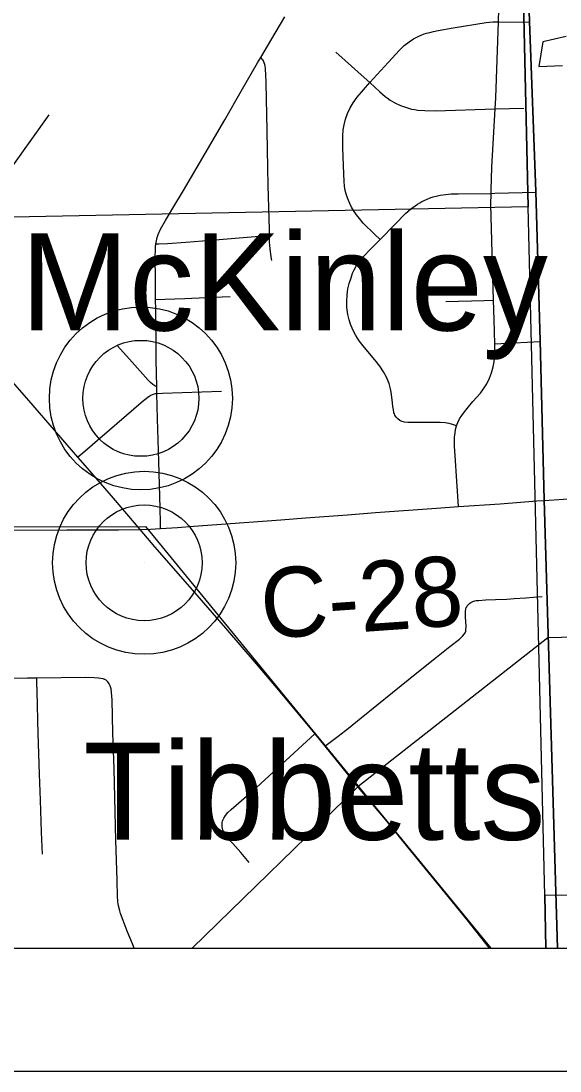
# Model space of a CAD drawing. Extents: x -6.4 to 34, y -4.2 to 22.
# Drawn here: x 6.676 to 7.115, y 14 to 14.854 of the extents above; entities that cross this region are included whole.
import ezdxf

# ---------------------------------------------------------------- set-up
doc = ezdxf.new("R2010")
doc.units = 0
for name, color, linetype in [('GM_X_Corporation', 7, 'Continuous'), ('GM_X_County_Road', 7, 'Continuous'), ('GM_X_County_Road_Text', 7, 'Continuous'), ('GM_X_Major_Lake', 7, 'Continuous'), ('GM_X_Rail_Line', 7, 'Continuous'), ('GM_X_State_Route', 7, 'Continuous'), ('GM_X_Township_Road', 7, 'Continuous'), ('GM_X_Unincorporated', 7, 'Continuous'), ('GM_X_Unincorporated_Location', 7, 'Continuous'), ('GM_X_Unincorporated_Text', 7, 'Continuous'), ('GM_X_US_Route', 7, 'Continuous'), ('SH_Data', 7, 'Continuous')]:
    doc.layers.add(name, color=color, linetype=linetype)

msp = doc.modelspace()

# ---------------------------------------------------------------- linework, layer by layer
at = {"layer": 'GM_X_Corporation'}
for points in [[(7.11238, 14.1), (8.9, 14.1), (8.9, 15.93563), (8.68149, 15.93107), (7.29257, 15.90442), (7.27024, 15.90398), (7.0636, 15.90143), (7.07436, 15.33931), (7.08969, 14.85359), (7.0948, 14.71527), (7.09827, 14.59391), (7.1017, 14.46462)], [(5.96082, 15.88441), (7.0606, 15.90739), (7.07836, 15.15585), (7.08872, 14.70278), (5.96639, 14.68043), (5.93632, 15.88385)], [(7.07836, 15.15585), (8.07052, 15.16463), (8.09545, 14.15347), (7.10212, 14.14277), (7.08872, 14.70278)], [(5.97939, 14.1), (7.10309, 14.1), (7.10212, 14.14277), (7.08872, 14.70278), (5.96639, 14.68043)], [(7.10309, 14.1), (8.09764, 14.1), (8.09545, 14.15347), (7.10212, 14.14277)]]:
    msp.add_lwpolyline(points, close=True, dxfattribs=at)
for points in [[(2.1, 14.1), (7.11238, 14.1), (7.1017, 14.46462), (7.09827, 14.59391), (7.0948, 14.71527), (7.08969, 14.85359), (7.07436, 15.33931), (7.0636, 15.90143), (6.86672, 15.89797), (6.75956, 15.89697), (6.5599, 15.89325), (5.71845, 15.87759)], [(7.28365, 14.35653), (7.10471, 14.3522), (6.95024, 14.23111), (6.81548, 14.1), (8.03838, 14.1)]]:
    msp.add_lwpolyline(points, dxfattribs=at)
at = {"layer": 'GM_X_County_Road'}
for points in [[(7.1019, 14.46407), (7.14832, 14.46726), (7.19036, 14.47035), (7.22929, 14.47351), (7.28617, 14.47742), (7.30838, 14.47886)], [(6.88773, 14.44828), (6.90771, 14.44975), (6.94173, 14.45238), (6.96463, 14.45413), (7.0142, 14.45777), (7.03193, 14.45897), (7.06576, 14.46127), (7.09558, 14.46363), (7.1019, 14.46407)], [(6.77298, 14.4403), (6.78162, 14.44071), (6.78977, 14.44108), (6.80358, 14.44201), (6.81682, 14.44307), (6.88773, 14.44828)]]:
    msp.add_lwpolyline(points, dxfattribs=at)
at = {"layer": 'GM_X_Major_Lake'}
msp.add_lwpolyline([(7.11943, 14.84121), (7.10048, 14.83712), (7.09733, 14.81701), (7.11664, 14.81768)], dxfattribs=at)
at = {"layer": 'GM_X_Rail_Line'}
msp.add_lwpolyline([(5.07851, 14.44212), (6.77749, 14.44289), (7.05826, 14.1)], dxfattribs=at)
at = {"layer": 'GM_X_State_Route'}
msp.add_lwpolyline([(6.62814, 14.44005), (6.66087, 14.43994), (6.71358, 14.44011), (6.75565, 14.44025), (6.77298, 14.4403)], dxfattribs=at)
at = {"layer": 'GM_X_Township_Road'}
msp.add_line((7.06461, 14.85335), (7.08989, 14.85303), dxfattribs=at)
for points in [[(7.03193, 14.45897), (7.02932, 14.50042), (7.02878, 14.50811), (7.02867, 14.51216), (7.02885, 14.51584), (7.02921, 14.51877), (7.02967, 14.5217), (7.0305, 14.52472), (7.0314, 14.52742), (7.03284, 14.5303), (7.03472, 14.5331), (7.03694, 14.53609), (7.04011, 14.54013), (7.04375, 14.54446), (7.04992, 14.55138), (7.05246, 14.55481), (7.05499, 14.55898), (7.05716, 14.56336), (7.05889, 14.56792), (7.0602, 14.57262), (7.06095, 14.57681), (7.06147, 14.58291), (7.06146, 14.59145), (7.06089, 14.61078), (7.06048, 14.62694), (7.06001, 14.64557), (7.05834, 14.70458), (7.05844, 14.71378), (7.05847, 14.71641), (7.05924, 14.73506), (7.06082, 14.7636), (7.06183, 14.78241), (7.06231, 14.79152), (7.06461, 14.85335), (7.0649, 14.86356)], [(6.78977, 14.44108), (6.78967, 14.44585), (6.78941, 14.45773), (6.78841, 14.49569), (6.78736, 14.53046), (6.78691, 14.55112), (6.78677, 14.55641), (6.78631, 14.57829), (6.78619, 14.58388), (6.78592, 14.6193), (6.78587, 14.62739), (6.78577, 14.64355), (6.78551, 14.66221), (6.78565, 14.6682), (6.78572, 14.67015), (6.78601, 14.67274), (6.78645, 14.67509), (6.78711, 14.67778), (6.78785, 14.68019), (6.7899, 14.68464), (6.79373, 14.6917), (6.79975, 14.70181), (6.80854, 14.71613), (6.82621, 14.74615), (6.84197, 14.77367), (6.85537, 14.79679), (6.86873, 14.81994), (6.87133, 14.82428), (6.87957, 14.83807), (6.88747, 14.85148), (6.89083, 14.85742)], [(6.96824, 14.67625), (6.96404, 14.68021), (6.95465, 14.68965), (6.95151, 14.69339), (6.94924, 14.69627), (6.94718, 14.69909), (6.94507, 14.70261), (6.94361, 14.7056), (6.94225, 14.7088), (6.94095, 14.71243), (6.93998, 14.71617), (6.93937, 14.71956), (6.93904, 14.72331), (6.9388, 14.72954), (6.93793, 14.75058), (6.93791, 14.76046), (6.93825, 14.76533), (6.93896, 14.76953), (6.94023, 14.77424), (6.9419, 14.77882), (6.944, 14.78323), (6.9465, 14.78742), (6.94973, 14.79189), (6.95488, 14.79803), (6.96008, 14.80381), (6.97479, 14.8202), (6.98398, 14.83024), (6.98796, 14.83405), (6.99179, 14.83705), (6.99538, 14.83935), (6.99713, 14.84031), (6.99971, 14.8416), (7.00169, 14.8424), (7.00423, 14.84345), (7.00609, 14.84401), (7.00863, 14.84471), (7.01165, 14.84542), (7.01552, 14.84622), (7.02759, 14.84836), (7.05438, 14.85264), (7.05998, 14.85315), (7.06461, 14.85335)], [(6.93233, 14.82863), (6.93978, 14.82182), (6.95543, 14.80794), (6.96008, 14.80381)], [(6.88026, 14.65909), (6.87977, 14.66209), (6.87935, 14.66451), (6.87908, 14.66634), (6.87883, 14.66879), (6.87849, 14.67434), (6.87845, 14.67936), (6.87841, 14.68424), (6.87743, 14.72024), (6.8769, 14.74942), (6.87655, 14.76493), (6.87576, 14.80342), (6.87545, 14.81086), (6.87527, 14.81393), (6.87509, 14.81553), (6.87485, 14.81713), (6.87452, 14.81854), (6.8741, 14.81991), (6.87377, 14.82075), (6.8734, 14.82156), (6.87293, 14.82226), (6.87241, 14.82302), (6.87133, 14.82428)], [(6.96008, 14.80381), (6.96814, 14.79633), (6.97243, 14.79262), (6.97413, 14.79137), (6.97653, 14.78966), (6.98034, 14.7874), (6.9849, 14.78521), (6.98966, 14.78347), (6.99394, 14.78234), (6.99612, 14.78192), (6.99893, 14.78149), (7.00458, 14.78104), (7.01334, 14.78101), (7.06183, 14.78241), (7.08506, 14.78309)], [(6.66176, 14.72481), (6.66976, 14.73609), (6.69925, 14.77771)], [(7.0305, 14.52472), (7.02722, 14.5258), (7.02448, 14.52655), (7.02125, 14.52709), (7.01721, 14.52738), (7.01013, 14.5275), (6.99081, 14.52742), (6.98822, 14.52764), (6.98627, 14.52816), (6.98529, 14.5286), (6.98444, 14.52907), (6.98279, 14.53027), (6.9814, 14.53177), (6.98078, 14.53266), (6.98032, 14.5335), (6.97989, 14.53443), (6.97958, 14.53538), (6.97906, 14.53799), (6.97865, 14.54041), (6.97829, 14.54333), (6.97781, 14.54802), (6.9773, 14.55199), (6.97678, 14.55475), (6.97561, 14.55908), (6.97349, 14.5642), (6.97114, 14.5685), (6.96809, 14.5731), (6.96388, 14.57841), (6.95553, 14.58849), (6.95132, 14.59395), (6.94856, 14.59819), (6.94618, 14.60265), (6.94419, 14.6073), (6.94303, 14.61094), (6.94207, 14.61527), (6.94134, 14.62091), (6.94115, 14.62596), (6.94139, 14.63102), (6.94175, 14.63398), (6.94209, 14.63603), (6.94258, 14.63825), (6.94311, 14.64035), (6.94469, 14.64516), (6.94598, 14.6489), (6.94727, 14.65159), (6.94891, 14.65452), (6.95108, 14.65786), (6.95442, 14.66213), (6.96081, 14.66874), (6.96824, 14.67625), (6.98026, 14.6884), (6.98902, 14.6973), (6.99324, 14.70107), (6.99676, 14.70376), (6.99859, 14.70501), (7.00052, 14.70612), (7.00221, 14.70706), (7.00424, 14.70804), (7.00666, 14.70914), (7.00886, 14.71001), (7.01154, 14.71083), (7.01373, 14.71145), (7.01701, 14.71223), (7.02177, 14.71285), (7.02603, 14.71326), (7.03182, 14.71346), (7.05844, 14.71378), (7.06147, 14.71388), (7.095, 14.71471)], [(6.78601, 14.67274), (6.78841, 14.67283), (6.79544, 14.67311), (6.81037, 14.67411), (6.83752, 14.67617), (6.86995, 14.67897), (6.87559, 14.67923), (6.87845, 14.67936)], [(6.78587, 14.62739), (6.79342, 14.6277), (6.8095, 14.62835), (6.82681, 14.62912), (6.84629, 14.62994)], [(7.02184, 14.62593), (7.05295, 14.62674), (7.06048, 14.62694)], [(6.78677, 14.55641), (6.78507, 14.55737), (6.78349, 14.55844), (6.78174, 14.55997), (6.77971, 14.56195), (6.77773, 14.56415), (6.76665, 14.57652), (6.7549, 14.58971)], [(7.06146, 14.59145), (7.06675, 14.59172), (7.09846, 14.59336)], [(6.78691, 14.55112), (6.7914, 14.55128), (6.83943, 14.55301)], [(6.72247, 14.49911), (6.72662, 14.50269), (6.77605, 14.5453), (6.78048, 14.54874), (6.78119, 14.54918), (6.78203, 14.54965), (6.78337, 14.55024), (6.78499, 14.55077), (6.78584, 14.55099), (6.78691, 14.55112)], [(7.04116, 14.38042), (7.04193, 14.38095), (7.04268, 14.38136), (7.04372, 14.3818), (7.04518, 14.38225), (7.04649, 14.38252), (7.0482, 14.38273), (7.05388, 14.38316), (7.06222, 14.38349), (7.07123, 14.38382), (7.07729, 14.38415), (7.08673, 14.38482), (7.09301, 14.3853), (7.10003, 14.38599)], [(6.92331, 14.26406), (6.93418, 14.27229), (6.94273, 14.27895), (6.95278, 14.2871), (6.97842, 14.30776), (6.99822, 14.3238), (7.01425, 14.33658), (7.02494, 14.34512), (7.03274, 14.35122), (7.0354, 14.35368), (7.03688, 14.35547), (7.03736, 14.35624), (7.03766, 14.35695), (7.03789, 14.35763), (7.03802, 14.35851), (7.03812, 14.36146), (7.03774, 14.36937), (7.03769, 14.37126), (7.03771, 14.3728), (7.03782, 14.37416), (7.03796, 14.37523), (7.03808, 14.37597), (7.03837, 14.37692), (7.03868, 14.37759), (7.03902, 14.37821), (7.03948, 14.37882), (7.04041, 14.37976), (7.04116, 14.38042)], [(6.62911, 14.31939), (6.63265, 14.31932), (6.67051, 14.31961), (6.68172, 14.31964), (6.6893, 14.31973), (6.72844, 14.32017), (6.7359, 14.32004), (6.73927, 14.31985), (6.74136, 14.31955), (6.74305, 14.31914), (6.7441, 14.31871)], [(6.6939, 14.17644), (6.69316, 14.19412), (6.69218, 14.22019), (6.69152, 14.24128), (6.69039, 14.27479), (6.69017, 14.28471), (6.68976, 14.29836), (6.68937, 14.31694), (6.6893, 14.31973)], [(6.7685, 14.1), (6.76714, 14.10353), (6.76283, 14.11379), (6.75936, 14.12235), (6.75738, 14.12818), (6.75681, 14.13018), (6.75575, 14.13422), (6.75539, 14.1362), (6.7552, 14.13731), (6.75506, 14.13841), (6.75484, 14.14177), (6.75446, 14.15517), (6.75341, 14.18742), (6.75321, 14.19922), (6.75201, 14.2458), (6.75115, 14.27497), (6.75047, 14.30178), (6.75027, 14.30484), (6.75002, 14.30788), (6.74963, 14.31093), (6.74895, 14.31331), (6.74814, 14.31498), (6.74706, 14.31648), (6.7457, 14.31776), (6.7441, 14.31871)], [(6.86177, 14.16947), (6.85516, 14.17771), (6.84846, 14.18505), (6.84437, 14.18972), (6.84219, 14.19275), (6.84148, 14.19403), (6.84103, 14.19494), (6.84058, 14.19603), (6.84025, 14.19728), (6.84002, 14.19846), (6.83991, 14.19974), (6.8399, 14.20098), (6.84002, 14.20222), (6.84021, 14.20322), (6.84045, 14.20403), (6.84119, 14.20573), (6.84252, 14.20782), (6.8445, 14.21022), (6.84719, 14.21279), (6.86785, 14.23066), (6.89852, 14.2588), (6.91512, 14.27414)]]:
    msp.add_lwpolyline(points, dxfattribs=at)
at = {"layer": 'GM_X_Unincorporated'}
for centre, radius in [((6.77386, 14.54706), 0.0744), ((6.77386, 14.54706), 0.04716), ((6.7765, 14.4133), 0.0744), ((6.7765, 14.4133), 0.04716)]:
    msp.add_circle(centre, radius, dxfattribs=at)
at = {"layer": 'GM_X_Unincorporated_Location'}
for p, q in [((6.77386, 14.54706), (6.77386, 14.54706)), ((6.7765, 14.4133), (6.7765, 14.4133))]:
    msp.add_line(p, q, dxfattribs=at)
at = {"layer": 'GM_X_US_Route'}
for points in [[(6.50619, 14.75363), (6.51226, 14.74582), (6.5181, 14.73808), (6.52368, 14.73059), (6.53018, 14.72228), (6.53724, 14.71356), (6.54415, 14.70508), (6.55738, 14.68978), (6.57938, 14.66362), (6.60073, 14.63826), (6.61765, 14.61972), (6.66368, 14.56671), (6.6825, 14.54524), (6.72247, 14.49911), (6.73008, 14.49032), (6.75129, 14.46598), (6.77298, 14.4403)], [(6.77298, 14.4403), (6.78498, 14.42623), (6.81739, 14.38927), (6.84255, 14.36025), (6.86766, 14.33105), (6.88574, 14.30972), (6.91512, 14.27414), (6.92331, 14.26406), (6.93604, 14.24837), (6.95044, 14.23056)], [(6.95044, 14.23056), (6.97373, 14.20283), (6.99054, 14.1821), (7.01486, 14.15217), (7.03884, 14.12283), (7.05702, 14.1)]]:
    msp.add_lwpolyline(points, dxfattribs=at)
at = {"layer": 'SH_Data'}
for p, q in [((2.1, 14.1), (8.9, 14.1)), ((2, 14), (9, 14))]:
    msp.add_line(p, q, dxfattribs=at)

# ---------------------------------------------------------------- texts
at = {"layer": 'GM_X_County_Road_Text'}
msp.add_text('C-28', height=0.056818, rotation=4.01417, dxfattribs=at).set_placement((6.87301, 14.35136))
at = {"layer": 'GM_X_Unincorporated_Text'}
for s, p in [('McKinley Heights', (6.67624, 14.60224)), ('Tibbetts Corners', (6.72707, 14.18808))]:
    msp.add_text(s, height=0.0789773, rotation=0.00001, dxfattribs=at).set_placement(p)

doc.saveas('drawing.dxf')
